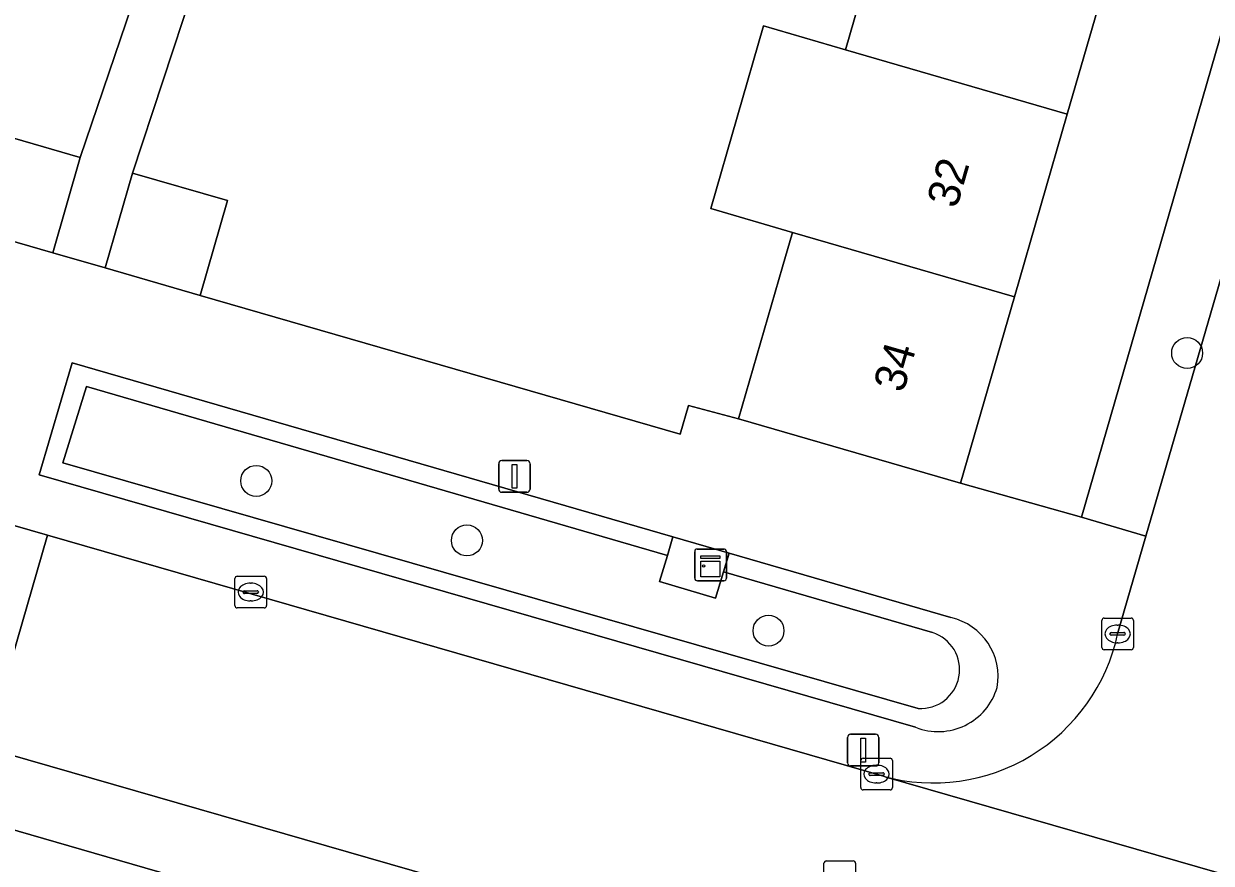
# Model space of a CAD drawing. Extents: x 159817 to 160765, y 380688 to 381638.
# Drawn here: x 160313.5 to 160351.02, y 381182.22 to 381208.73 of the extents above; entities that cross this region are included whole.
import ezdxf

# ---------------------------------------------------------------- set-up
doc = ezdxf.new("R2010")
doc.units = 0
for name, color, linetype in [('IMGEO_Boom', 7, 'Continuous'), ('IMGEO_Erf', 7, 'Continuous'), ('IMGEO_Groenvoorziening', 7, 'Continuous'), ('IMGEO_Haag', 7, 'Continuous'), ('IMGEO_Kast', 7, 'Continuous'), ('IMGEO_Kolk', 7, 'Continuous'), ('IMGEO_Lichtmast', 7, 'Continuous'), ('IMGEO_Muur', 7, 'Continuous'), ('IMGEO_Pand', 7, 'Continuous'), ('IMGEO_Pand_nummerreeks', 7, 'Continuous'), ('IMGEO_Rijbaan_lokaal_open', 7, 'Continuous'), ('IMGEO_Rioolput', 7, 'Continuous'), ('IMGEO_Voetpad_open', 7, 'Continuous')]:
    doc.layers.add(name, color=color, linetype=linetype)

msp = doc.modelspace()

# ---------------------------------------------------------------- linework, layer by layer
at = {"layer": 'IMGEO_Boom'}
for centre in [(160350.261, 381198.331), (160320.847, 381194.291), (160327.504, 381192.41), (160337.033, 381189.561)]:
    msp.add_circle(centre, 0.489, dxfattribs=at)
at = {"layer": 'IMGEO_Erf'}
for points in [[(160341.134, 381213.682), (160336.63, 381214.99), (160338.333, 381220.87), (160326.797, 381224.131), (160325.699, 381220.903), (160323.007, 381221.818), (160320.927, 381215.901), (160326.748, 381213.854), (160326.183, 381212.249), (160325.637, 381210.696), (160319.817, 381212.743), (160316.937, 381204.012), (160319.941, 381203.144), (160319.076, 381200.152), (160334.238, 381195.771), (160334.506, 381196.675), (160336.086, 381196.253), (160337.477, 381201.056), (160337.791, 381202.142), (160335.207, 381202.892), (160336.879, 381208.662), (160339.463, 381207.912)], [(160353.653, 381216.434), (160349.848, 381217.533), (160348.143, 381211.647), (160346.472, 381205.877), (160344.801, 381200.107), (160343.097, 381194.222), (160346.926, 381193.142)]]:
    msp.add_lwpolyline(points, close=True, dxfattribs=at)
for points in [[(160296.975, 381213.895), (160294.599, 381207.871), (160295.955, 381207.43), (160295.833, 381206.867), (160305.747, 381204.003), (160306.714, 381207.349), (160311.053, 381206.095), (160310.912, 381205.606), (160312.018, 381205.287), (160311.193, 381202.43), (160311.43, 381202.361), (160312.298, 381205.367), (160315.285, 381204.504), (160317.641, 381211.453)], [(160329.156, 381178.647), (160278.3, 381193.36)]]:
    msp.add_lwpolyline(points, dxfattribs=at)
at = {"layer": 'IMGEO_Groenvoorziening'}
for points in [[(160341.76, 381187.106), (160314.739, 381194.861), (160315.481, 381197.269), (160333.837, 381191.934), (160334.012, 381192.521), (160315.034, 381198.022), (160313.991, 381194.487), (160341.683, 381186.509)], [(160315.481, 381197.269), (160314.739, 381194.861), (160341.76, 381187.106)], [(160342.21, 381189.5), (160335.61, 381191.418), (160335.36, 381190.585), (160333.593, 381191.116), (160333.837, 381191.934), (160315.481, 381197.269)], [(160342.797, 381189.975), (160335.787, 381192.007), (160335.61, 381191.418), (160342.21, 381189.5)]]:
    msp.add_lwpolyline(points, dxfattribs=at)
for centre, radius, start, end in [((160342.367, 381188.103), 1.921, 349.8272, 77.0491), ((160341.844, 381188.33), 1.226, 266.0867, 72.622), ((160341.844, 381188.33), 1.226, 266.0867, 72.622), ((160342.395, 381188.315), 1.942, 248.4831, 343.5017)]:
    msp.add_arc(centre, radius, start, end, dxfattribs=at)
at = {"layer": 'IMGEO_Haag'}
for points in [[(160341.76, 381187.106), (160314.739, 381194.861), (160315.481, 381197.269), (160333.837, 381191.934), (160334.012, 381192.521), (160315.034, 381198.022), (160313.991, 381194.487), (160341.683, 381186.509)], [(160342.797, 381189.975), (160335.787, 381192.007), (160335.61, 381191.418), (160342.21, 381189.5)]]:
    msp.add_lwpolyline(points, dxfattribs=at)
for centre, radius, start, end in [((160342.367, 381188.103), 1.921, 349.8272, 77.0491), ((160341.844, 381188.33), 1.226, 266.0867, 72.622), ((160342.395, 381188.315), 1.942, 248.4831, 343.5017)]:
    msp.add_arc(centre, radius, start, end, dxfattribs=at)
at = {"layer": 'IMGEO_Kast'}
for p, q in [((160334.701, 381191.215), (160334.701, 381192.056)), ((160334.701, 381192.056), (160334.701, 381191.215)), ((160334.776, 381192.14), (160335.617, 381192.14)), ((160335.617, 381192.14), (160334.776, 381192.14)), ((160335.701, 381192.065), (160335.701, 381191.224)), ((160335.701, 381191.224), (160335.701, 381192.065)), ((160335.626, 381191.14), (160334.785, 381191.14)), ((160334.785, 381191.14), (160335.626, 381191.14))]:
    msp.add_line(p, q, dxfattribs=at)
for points in [[(160334.896, 381191.93), (160335.496, 381191.93), (160335.496, 381191.845), (160334.896, 381191.845), (160334.896, 381191.93)], [(160334.896, 381191.755), (160335.496, 381191.755), (160335.496, 381191.266), (160334.896, 381191.266), (160334.896, 381191.755)]]:
    msp.add_lwpolyline(points, dxfattribs=at)
msp.add_circle((160334.98, 381191.604), 0.0377, dxfattribs=at)
for centre, start, end in [((160334.779, 381192.062), 92.4484, 184.2845), ((160334.779, 381192.062), 92.4484, 184.2845), ((160335.623, 381192.062), 2.4484, 94.2845), ((160335.623, 381192.062), 2.4484, 94.2845), ((160334.779, 381191.218), 182.4484, 274.2845), ((160334.779, 381191.218), 182.4484, 274.2845), ((160335.623, 381191.218), 272.4484, 4.2845), ((160335.623, 381191.218), 272.4484, 4.2845)]:
    msp.add_arc(centre, 0.0779, start, end, dxfattribs=at)
at = {"layer": 'IMGEO_Kolk'}
for p, q in [((160320.173, 381190.354), (160320.173, 381191.206)), ((160320.248, 381191.28), (160321.1, 381191.28)), ((160321.174, 381191.206), (160321.174, 381190.354)), ((160320.432, 381190.774), (160320.432, 381190.786)), ((160320.87, 381190.737), (160320.472, 381190.737)), ((160320.475, 381190.823), (160320.873, 381190.823)), ((160320.661, 381191.06), (160320.686, 381191.06)), ((160320.916, 381190.786), (160320.916, 381190.774)), ((160320.684, 381190.5), (160320.659, 381190.5)), ((160321.1, 381190.28), (160320.248, 381190.28)), ((160347.564, 381189.032), (160347.564, 381189.884)), ((160347.639, 381189.958), (160348.491, 381189.958)), ((160348.052, 381189.738), (160348.077, 381189.738)), ((160348.565, 381189.884), (160348.565, 381189.032)), ((160347.823, 381189.452), (160347.823, 381189.464)), ((160348.261, 381189.415), (160347.863, 381189.415)), ((160347.866, 381189.501), (160348.264, 381189.501)), ((160348.307, 381189.464), (160348.307, 381189.452)), ((160348.491, 381188.958), (160347.639, 381188.958)), ((160348.075, 381189.178), (160348.05, 381189.178)), ((160340.022, 381185.53), (160340.874, 381185.53)), ((160339.947, 381184.604), (160339.947, 381185.456)), ((160340.435, 381185.31), (160340.46, 381185.31)), ((160340.948, 381185.456), (160340.948, 381184.604)), ((160340.206, 381185.024), (160340.206, 381185.036)), ((160340.644, 381184.987), (160340.246, 381184.987)), ((160340.249, 381185.073), (160340.647, 381185.073)), ((160340.458, 381184.75), (160340.433, 381184.75)), ((160340.69, 381185.036), (160340.69, 381185.024)), ((160340.874, 381184.53), (160340.022, 381184.53))]:
    msp.add_line(p, q, dxfattribs=at)
for points in [[(160320.173, 381190.354), (160320.173, 381191.206)], [(160320.248, 381191.28), (160321.1, 381191.28)], [(160321.174, 381191.206), (160321.174, 381190.354)], [(160321.1, 381190.28), (160320.248, 381190.28)], [(160347.564, 381189.032), (160347.564, 381189.884)], [(160347.639, 381189.958), (160348.491, 381189.958)], [(160348.565, 381189.884), (160348.565, 381189.032)], [(160348.491, 381188.958), (160347.639, 381188.958)], [(160340.022, 381185.53), (160340.874, 381185.53)], [(160339.947, 381184.604), (160339.947, 381185.456)], [(160340.948, 381185.456), (160340.948, 381184.604)], [(160340.874, 381184.53), (160340.022, 381184.53)]]:
    msp.add_lwpolyline(points, dxfattribs=at)
for centre, radius, start, end in [((160320.25, 381191.204), 0.0765, 91.552, 178.448), ((160320.25, 381191.204), 0.0765, 91.552, 178.448), ((160321.098, 381191.204), 0.0765, 1.552, 88.448), ((160321.098, 381191.204), 0.0765, 1.552, 88.448), ((160320.472, 381190.783), 0.0403, 85.8775, 175.7526), ((160320.469, 381190.773), 0.0366, 178.938, 274.7102), ((160320.873, 381190.78), 0.043, 264.8664, 352.4533), ((160320.877, 381190.785), 0.0386, 1.7309, 96.639), ((160320.25, 381190.356), 0.0765, 181.552, 268.448), ((160320.25, 381190.356), 0.0765, 181.552, 268.448), ((160321.098, 381190.356), 0.0765, 271.552, 358.448), ((160321.098, 381190.356), 0.0765, 271.552, 358.448), ((160347.641, 381189.882), 0.0765, 91.552, 178.448), ((160347.641, 381189.882), 0.0765, 91.552, 178.448), ((160348.489, 381189.882), 0.0765, 1.552, 88.448), ((160348.489, 381189.882), 0.0765, 1.552, 88.448), ((160347.863, 381189.461), 0.0403, 85.8775, 175.7526), ((160347.86, 381189.451), 0.0366, 178.938, 274.7102), ((160348.264, 381189.458), 0.043, 264.8664, 352.4533), ((160348.268, 381189.463), 0.0386, 1.7309, 96.639), ((160347.641, 381189.034), 0.0765, 181.552, 268.448), ((160347.641, 381189.034), 0.0765, 181.552, 268.448), ((160348.489, 381189.034), 0.0765, 271.552, 358.448), ((160348.489, 381189.034), 0.0765, 271.552, 358.448), ((160340.024, 381185.454), 0.0765, 91.552, 178.448), ((160340.024, 381185.454), 0.0765, 91.552, 178.448), ((160340.872, 381185.454), 0.0765, 1.552, 88.448), ((160340.872, 381185.454), 0.0765, 1.552, 88.448), ((160340.246, 381185.033), 0.0403, 85.8775, 175.7526), ((160340.243, 381185.023), 0.0366, 178.938, 274.7102), ((160340.647, 381185.03), 0.043, 264.8664, 352.4533), ((160340.651, 381185.035), 0.0386, 1.7309, 96.639), ((160340.024, 381184.606), 0.0765, 181.552, 268.448), ((160340.024, 381184.606), 0.0765, 181.552, 268.448), ((160340.872, 381184.606), 0.0765, 271.552, 358.448), ((160340.872, 381184.606), 0.0765, 271.552, 358.448)]:
    msp.add_arc(centre, radius, start, end, dxfattribs=at)
for centre, major_axis, ratio, start_param, end_param in [((160320.66, 381190.78), (-0.387, 0.002), 0.722429, 4.712389, 7.853982), ((160320.685, 381190.78), (-0.39, 0.002), 0.717154, 1.570796, 4.712389), ((160348.051, 381189.458), (-0.387, 0.002), 0.722429, 4.712389, 7.853982), ((160348.076, 381189.458), (-0.39, 0.002), 0.717154, 1.570796, 4.712389), ((160340.434, 381185.03), (-0.387, 0.002), 0.722429, 4.712389, 7.853982), ((160340.459, 381185.03), (-0.39, 0.002), 0.717154, 1.570796, 4.712389)]:
    msp.add_ellipse(centre, major_axis=major_axis, ratio=ratio, start_param=start_param, end_param=end_param, dxfattribs=at)
at = {"layer": 'IMGEO_Lichtmast'}
for p, q in [((160328.609, 381194.933), (160329.399, 381194.933)), ((160329.399, 381194.933), (160328.609, 381194.933)), ((160328.509, 381194.033), (160328.509, 381194.833)), ((160328.509, 381194.833), (160328.509, 381194.033)), ((160329.499, 381194.833), (160329.499, 381194.033)), ((160329.499, 381194.033), (160329.499, 381194.833)), ((160329.399, 381193.933), (160328.609, 381193.933)), ((160328.609, 381193.933), (160329.399, 381193.933)), ((160339.629, 381186.287), (160340.419, 381186.287)), ((160340.419, 381186.287), (160339.629, 381186.287)), ((160339.529, 381185.387), (160339.529, 381186.187)), ((160339.529, 381186.187), (160339.529, 381185.387)), ((160340.519, 381186.187), (160340.519, 381185.387)), ((160340.519, 381185.387), (160340.519, 381186.187)), ((160340.419, 381185.287), (160339.629, 381185.287)), ((160339.629, 381185.287), (160340.419, 381185.287))]:
    msp.add_line(p, q, dxfattribs=at)
for points in [[(160328.929, 381194.808), (160329.079, 381194.808), (160329.079, 381194.058), (160328.929, 381194.058), (160328.929, 381194.808)], [(160339.949, 381186.162), (160340.099, 381186.162), (160340.099, 381185.412), (160339.949, 381185.412), (160339.949, 381186.162)]]:
    msp.add_lwpolyline(points, dxfattribs=at)
for centre, start, end in [((160328.609, 381194.833), 90, 180), ((160328.609, 381194.833), 90, 180), ((160329.399, 381194.833), 0, 90), ((160329.399, 381194.833), 360, 90), ((160328.609, 381194.033), 180, 270), ((160328.609, 381194.033), 180, 270), ((160329.399, 381194.033), 270, 0), ((160329.399, 381194.033), 270, 0), ((160339.629, 381186.187), 90, 180), ((160339.629, 381186.187), 90, 180), ((160340.419, 381186.187), 0, 90), ((160340.419, 381186.187), 360, 90), ((160339.629, 381185.387), 180, 270), ((160339.629, 381185.387), 180, 270), ((160340.419, 381185.387), 270, 0), ((160340.419, 381185.387), 270, 0)]:
    msp.add_arc(centre, 0.1, start, end, dxfattribs=at)
at = {"layer": 'IMGEO_Muur'}
msp.add_lwpolyline([(160334.506, 381196.675), (160336.086, 381196.253)], dxfattribs=at)
at = {"layer": 'IMGEO_Pand'}
for points in [[(160346.472, 381205.877), (160348.143, 381211.647), (160341.134, 381213.682), (160339.463, 381207.912)], [(160346.472, 381205.877), (160339.463, 381207.912), (160336.879, 381208.662), (160335.207, 381202.892), (160337.791, 381202.142), (160344.801, 381200.107)], [(160315.285, 381204.504), (160312.298, 381205.367), (160311.43, 381202.361), (160314.417, 381201.498)], [(160316.072, 381201.02), (160319.076, 381200.152), (160319.941, 381203.144), (160316.937, 381204.012)], [(160337.791, 381202.142), (160337.477, 381201.056), (160336.086, 381196.253), (160343.097, 381194.222), (160344.801, 381200.107)]]:
    msp.add_lwpolyline(points, close=True, dxfattribs=at)
at = {"layer": 'IMGEO_Rijbaan_lokaal_open'}
for points in [[(160368.215, 381234.221), (160370.337, 381241.568), (160363.734, 381243.436), (160361.67, 381236.217), (160348.958, 381192.55), (160348.065, 381189.456)], [(160340.664, 381184.965), (160340.752, 381184.93), (160358.49, 381179.827), (160358.816, 381179.79)]]:
    msp.add_lwpolyline(points, dxfattribs=at)
for points in [[(160314.255, 381192.573), (160311.651, 381193.323), (160309.697, 381186.611), (160312.301, 381185.861)], [(160340.664, 381184.965), (160314.255, 381192.573), (160312.301, 381185.861), (160329.797, 381180.826), (160329.938, 381180.803), (160346.8, 381175.9), (160346.957, 381175.818), (160373.409, 381168.155), (160375.389, 381174.985), (160358.816, 381179.79), (160358.49, 381179.827), (160340.752, 381184.93)]]:
    msp.add_lwpolyline(points, close=True, dxfattribs=at)
msp.add_arc((160342.243, 381190.707), 5.955, 254.6292, 347.8703, dxfattribs=at)
at = {"layer": 'IMGEO_Rioolput'}
for p, q in [((160338.785, 381181.363), (160338.785, 381182.215)), ((160338.86, 381182.289), (160339.712, 381182.289)), ((160339.786, 381182.215), (160339.786, 381181.363))]:
    msp.add_line(p, q, dxfattribs=at)
for points in [[(160338.785, 381181.363), (160338.785, 381182.215)], [(160338.86, 381182.289), (160339.712, 381182.289)], [(160339.786, 381182.215), (160339.786, 381181.363)]]:
    msp.add_lwpolyline(points, dxfattribs=at)
for centre, start, end in [((160338.862, 381182.213), 91.552, 178.448), ((160338.862, 381182.213), 91.552, 178.448), ((160339.71, 381182.213), 1.552, 88.448), ((160339.71, 381182.213), 1.552, 88.448)]:
    msp.add_arc(centre, 0.0765, start, end, dxfattribs=at)
at = {"layer": 'IMGEO_Voetpad_open'}
for points in [[(160378.693, 381297.546), (160377.296, 381298.306), (160367.267, 381263.577), (160366.293, 381260.204), (160363.346, 381250), (160354.607, 381219.739), (160353.653, 381216.434), (160346.926, 381193.142), (160348.958, 381192.55), (160361.67, 381236.217), (160363.734, 381243.436), (160364.487, 381246.013)], [(160319.076, 381200.152), (160316.072, 381201.02), (160314.417, 381201.498), (160311.43, 381202.361), (160311.193, 381202.43), (160311.111, 381202.147), (160305.665, 381203.72), (160305.747, 381204.003), (160295.833, 381206.867), (160295.955, 381207.43), (160294.599, 381207.871), (160287.303, 381210.745), (160282.201, 381212.828), (160280.923, 381213.109), (160279.777, 381209.999), (160277.458, 381210.919)], [(160317.641, 381211.453), (160315.285, 381204.504), (160314.417, 381201.498), (160316.072, 381201.02), (160316.937, 381204.012), (160319.817, 381212.743)], [(160276.377, 381203.813), (160277.528, 381203.235), (160277.992, 381203.077), (160279.332, 381202.672), (160282.041, 381201.853), (160311.651, 381193.323), (160314.255, 381192.573), (160340.664, 381184.965)], [(160348.065, 381189.456), (160348.958, 381192.55), (160346.926, 381193.142), (160343.097, 381194.222), (160336.086, 381196.253), (160334.506, 381196.675), (160334.238, 381195.771), (160319.076, 381200.152)], [(160341.683, 381186.509), (160313.991, 381194.487), (160315.034, 381198.022)], [(160315.034, 381198.022), (160334.012, 381192.521), (160335.787, 381192.007), (160342.797, 381189.975)], [(160329.797, 381180.826), (160312.301, 381185.861), (160309.697, 381186.611), (160281.102, 381194.84)], [(160278.3, 381193.36), (160329.156, 381178.647)]]:
    msp.add_lwpolyline(points, dxfattribs=at)
msp.add_lwpolyline([(160335.787, 381192.007), (160334.012, 381192.521), (160333.837, 381191.934), (160333.593, 381191.116), (160335.36, 381190.585), (160335.61, 381191.418)], close=True, dxfattribs=at)
for centre, radius, start, end in [((160342.367, 381188.103), 1.921, 349.8272, 77.0491), ((160342.243, 381190.707), 5.955, 254.6292, 347.8703), ((160342.395, 381188.315), 1.942, 248.4831, 343.5017)]:
    msp.add_arc(centre, radius, start, end, dxfattribs=at)

# ---------------------------------------------------------------- texts
at = {"layer": 'IMGEO_Pand_nummerreeks'}
for s, rotation, p in [('32', 73.8485, (160342.977, 381202.867)), ('34', 73.8487, (160341.291, 381197.044))]:
    msp.add_text(s, height=1, rotation=rotation, dxfattribs=at).set_placement(p)

doc.saveas('drawing.dxf')
